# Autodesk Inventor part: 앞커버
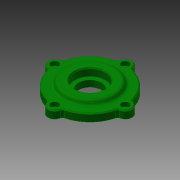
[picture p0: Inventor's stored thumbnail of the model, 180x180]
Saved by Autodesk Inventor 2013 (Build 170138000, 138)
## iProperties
Company: 한국ATC센터
Created: 2015-12
Part Number: 앞커버
Document SubType Name: Modeling
Designer: mdu
Density: 1 g/cm^3
Material: 알루미늄 6061
Author: mdu
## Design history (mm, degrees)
sketch "스케치1"
  geometry: C1 r 1.621 at (0, 6.75) reference; C2 r 1.621 at (-37, -30.25) reference; C3 r 1.621 at (0, -67.25) reference; C4 r 1.621 at (37, -30.25) reference; C5 r 10 at (0, -30.25) reference; C6 r 12 at (0, -30.25); C7 r 24.5 at (0, -30.25) reference; A1 r 3 centre (-38.77, -20.408) between (-38.239, -23.361) and (-35.862, -21.146) reference; A2 r 7 centre (-37, -30.25) between (-38.239, -23.361) and (-38.239, -37.139) reference; A3 r 3 centre (-38.77, -40.092) between (-35.862, -39.354) and (-38.239, -37.139) reference; A4 r 37 centre (0, -30.25) between (-35.862, -39.354) and (-9.104, -66.113) reference; A5 r 3 centre (-9.842, -69.02) between (-6.889, -68.489) and (-9.104, -66.113) reference; A6 r 7 centre (0, -67.25) between (-6.889, -68.489) and (6.889, -68.489) reference; A7 r 3 centre (9.842, -69.02) between (9.104, -66.112) and (6.889, -68.489) reference; A8 r 37 centre (0, -30.25) between (9.104, -66.112) and (35.863, -39.354) reference; A9 r 3 centre (38.77, -40.092) between (38.239, -37.139) and (35.863, -39.354) reference; A10 r 7 centre (37, -30.25) between (38.239, -37.139) and (38.239, -23.361) reference; A11 r 3 centre (38.77, -20.408) between (35.863, -21.146) and (38.239, -23.361) reference; A12 r 37 centre (0, -30.25) between (35.863, -21.146) and (9.104, 5.612) reference; A13 r 3 centre (9.842, 8.52) between (6.889, 7.989) and (9.104, 5.612) reference; A14 r 7 centre (0, 6.75) between (6.889, 7.989) and (-6.889, 7.989) reference; A15 r 3 centre (-9.842, 8.52) between (-9.104, 5.612) and (-6.889, 7.989) reference; A16 r 37 centre (0, -30.25) between (-9.104, 5.612) and (-35.862, -21.146) reference; 1 further point
  constraints: 1 centre point, 1 coincident
  dimensions: "d2" = 2 radial gap between concentric circles of C6 C5
extrude "돌출1" new body sketch "스케치1" distance "d0" = 8; taper "d1" = 0 deg
sketch "스케치2"
  geometry: C1 r 23.5 at (0, -30.25) reference; C2 r 12 at (0, -30.25) reference; 1 further point
extrude "돌출2" join sketch "스케치2" distance "d4" = 6; taper "d5" = 0 deg
sketch "스케치9"
  geometry: C1 r 21 at (0, 0); C2 r 23.5 at (0, 0) reference; 1 further point
  constraints: 1 centre point, 1 coincident
  dimensions: "d60" = 42 diameter of C1
extrude "돌출6" cut sketch "스케치9" distance "d63" = 3; taper "d64" = 0 deg
node "작업 평면1"
sketch "스케치4"
  geometry: C1 r 12 at (0, -30.25) reference; C2 r 27 at (0, -30.25); 1 further point
  constraints: 1 centre point
  dimensions: "d10" = 15 radial gap between concentric circles of C1 C2
extrude "돌출4" join sketch "스케치4" distance "d11" = 4; taper "d12" = -20 deg
fillet "모깎기2" dims "d13" = 3
node "작업점1"
  node "작업축1"
chamfer "모따기2" distance "d24" = 1; stored, may be unused: second distance "d25" = 2, angle "d26" = 45 deg
hole "구멍6" diameter "d43" = 4.5; stored, may be unused: countersink angle "d47" = 90 deg, drill point angle "d49" = 118 deg; dims "d41" = 10, "d42" = 10, "d44" = 6, "d45" = 8, "d46" = 4.4, "d48" = 8
sketch "스케치8"
  geometry: C1 r 13.456 at (0, 0) reference; C2 r 16 at (0, 0); 1 further point
  constraints: 1 centre point, 1 coincident
  dimensions: "d53" = 32 diameter of C2
extrude "돌출5" cut sketch "스케치8" distance "d54" = 8.3; taper "d55" = 0 deg
fillet "모깎기3" dims "d56" = 0.3
chamfer "모따기3" distance "d57" = 1.2; stored, may be unused: second distance "d58" = 2, angle "d59" = 30 deg
node "솔리드1"
pattern_circular "원형 패턴1" dims angle "d51" = 360 deg
node "참조1"
node "참조2"
